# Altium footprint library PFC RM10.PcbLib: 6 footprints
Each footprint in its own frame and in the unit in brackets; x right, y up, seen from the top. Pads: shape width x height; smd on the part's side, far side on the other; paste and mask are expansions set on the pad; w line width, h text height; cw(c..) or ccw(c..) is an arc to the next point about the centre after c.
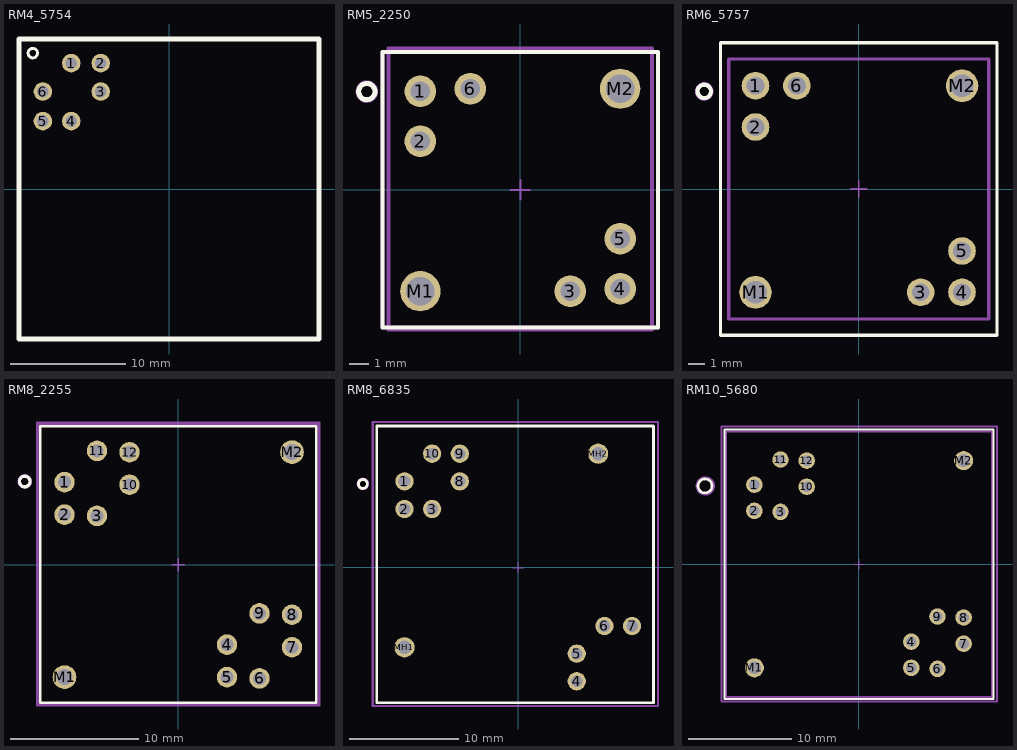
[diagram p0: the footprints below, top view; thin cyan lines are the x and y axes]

## RM4_5754 [mm] "THT, Body 11.44x11.44mm, 6Pin, Pitch 2.54mm"
height 11.18
pads (6):
  round 1.62 hole 1.02: 1(-8.525,10.975) 2(-5.95,10.975) 3(-5.95,8.5) 4(-8.525,5.925) 5(-11,5.925) 6(-11,8.5)
Top Overlay:
  circle w0.254: c-11.875,11.85 r0.412
  lines w0.4: -13.08,-13.08 13.08,-13.08 13.08,13.08 -13.08,13.08 -13.08,-13.08

## RM5_2250 [mm] "THT, Body 13.97x13.97mm, 6Pin, Pitch 2.54mm"
height 11.18
pads (8):
  round 1.6 hole 1: 1(-5.08,5.015) 2(-5.08,2.475) 3(2.54,-5.145) 4(5.08,-5.015) 5(5.08,-2.475) 6(-2.54,5.145)
  round 2.05 hole 1.45: M1(-5.08,-5.145) M2(5.08,5.145)
Top Overlay:
  circle w0.254: c-7.8,5 r0.412
  lines w0.2: -7.01,-6.99 6.99,-6.99 6.99,7.01 -7.01,7.01 -7.01,-6.99
Mechanical 13:
  circle w0.254: c-7.8,5 r0.447
  lines w0.2: -6.7,-7.1 -6.7,7.2 6.7,7.2 6.7,-7.1 -6.7,-7.1
Mechanical 15:
  lines w0.1: -0.5,0.005 0.5,0.005 ; 0,-0.495 0,0.505
  lines w0.2: -7,-7 -7,7 7,7 7,-7 -7,-7
  text ".Designator" at 0,0.005 h0.5
3D body "RM5_2250_0056.step": height 11.13, standoff -2.77, extent -6.532,-6.902 6.7,6.902

## RM6_5757 [mm] "THT, Body 16.64x17.65mm, 6Pin, Pitch 2.54mm"
height 13.21
pads (8):
  round 1.7 hole 1.1: 1(-6.35,6.35) 2(-6.35,3.81) 3(3.81,-6.35) 4(6.35,-6.35) 5(6.35,-3.81) 6(-3.81,6.35)
  round 2 hole 1.4: M1(-6.35,-6.35) M2(6.35,6.35)
Top Overlay:
  circle w0.254: c-9.5,6 r0.412
  lines w0.2: -8.5,-9 8.5,-9 8.5,9 -8.5,9 -8.5,-9
Mechanical 13:
  circle w0.254: c-9.5,6 r0.447
  lines w0.2: -8,-8 -8,8 8,8 8,-8 -8,-8
Mechanical 15:
  lines w0.1: -0.5,0 0.5,0 ; 0,-0.5 0,0.5
  text ".Designator" at 0,0 h0.5
3D body "RM6_5757_0222.step": height 13.05, standoff -3.37, extent -7.72,-7.71 7.7,7.71

## RM8_2255 [mm] "THT, Body 21.59x12.59mm, 12Pin, Pitch 2.54mm"
height 17.27
pads (14):
  round 1.6 hole 1: 1(-8.89,6.45) 2(-8.89,3.91) 3(-6.35,3.81) 4(3.81,-6.25) 5(3.81,-8.79) 6(6.35,-8.89) 7(8.89,-6.45) 8(8.89,-3.91) 9(6.35,-3.81) 10(-3.81,6.25) 11(-6.35,8.89) 12(-3.81,8.79)
  round 1.85 hole 1.25: M1(-8.89,-8.79) M2(8.89,8.79)
Top Overlay:
  circle w0.254: c-12,6.5 r0.412
  lines w0.2: -10.8,-10.8 10.8,-10.8 10.8,10.8 -10.8,10.8 -10.8,-10.8
Mechanical 13:
  circle w0.254: c-12,6.5 r0.447
  lines w0.2: -11,-11 11,-11 11,11.1 -11,11.1 -11,-11
Mechanical 15:
  lines w0.1: -0.5,0 0.5,0 ; 0,-0.5 0,0.5
  lines w0.2: -11,-11 11,-11 11,11 -11,11 -11,-11
  text ".Designator" at 0,0 h0.5
3D body "RM8_2255_0050.STEP": height 16.89, standoff -2.71, extent -10.761,-10.722 10.761,10.8

## RM8_6835 [mm] "THT, Body 24.64X24.64mm, 10Pin, Pitch 2.54mm"
height 17.32
pads (12):
  round 1.68 hole 1.07: 1(-10.45,7.91) 2(-10.45,5.37) 3(-7.91,5.37) 4(5.37,-10.45) 5(5.37,-7.91) 6(7.91,-5.37) 7(10.45,-5.37) 8(-5.37,7.91) 9(-5.37,10.45) 10(-7.91,10.45)
  round 1.86 hole 1.25: MH1(-10.45,-7.33) MH2(7.33,10.45)
Top Overlay:
  circle w0.254: c-14.27,7.67 r0.412
  lines w0.254: -12.99,-12.41 -12.99,12.99 12.41,12.99 12.41,-12.41 -12.99,-12.41
Mechanical 13:
  circle w0.254: c-14.27,7.67 r0.447
Mechanical 15:
  lines w0.1: -0.495,-0.005 0.505,-0.005 ; 0.005,-0.505 0.005,0.495
  lines w0.2: -13.37,-12.73 -13.37,13.37 12.83,13.37 12.83,-12.73 -13.37,-12.73
  text ".Designator" at 0,0 h0.5
3D body "RM8_6835.STEP": height 16.79, standoff -3.46, extent -12.35,-12.148 12.197,12.398

## RM10_5680 [mm] "THT, Body 26.16x26.16mm, 12Pin, Pitch 2.54mm"
height 19.05
pads (14):
  round 1.6 hole 1: 1(-10.16,7.72) 2(-10.16,5.18) 3(-7.62,5.08) 4(5.08,-7.52) 5(5.08,-10.06) 6(7.62,-10.16) 7(10.16,-7.72) 8(10.16,-5.18) 9(7.62,-5.08) 10(-5.08,7.52) 11(-7.62,10.16) 12(-5.08,10.06)
  round 1.85 hole 1.25: M1(-10.16,-10.06) M2(10.16,10.06)
Top Overlay:
  circle w0.254: c-14.95,7.6 r0.68
  lines w0.2: -13.08,-13.08 -13.08,13.08 13.08,13.08 13.08,-13.08 -13.08,-13.08
Mechanical 13:
  circle w0.254: c-14.92,7.6 r0.81
  lines w0.2: -12.9,-12.9 -12.9,12.9 12.9,12.9 12.9,-12.9 -12.9,-12.9
Mechanical 15:
  lines w0.1: -0.49,0 0.51,0 ; 0.01,-0.5 0.01,0.5
  lines w0.2: -13.36,-13.34 -13.36,13.38 13.4,13.38 13.4,-13.34 -13.36,-13.34
  text ".Designator" at 0.01,0 h0.5
3D body "RM10_5680_0009.step": height 19.17, standoff -2.23, extent -12.911,-12.868 12.911,12.953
